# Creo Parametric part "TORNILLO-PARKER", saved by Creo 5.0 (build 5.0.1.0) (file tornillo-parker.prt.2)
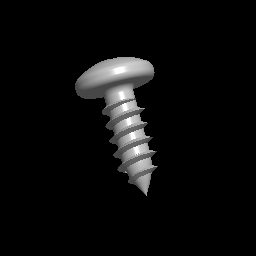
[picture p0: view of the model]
Units: millimeter Kilogram Sec (mmKs); MM, KILOGRAM, SECS
Materials in the file: FE40, ACERO

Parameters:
  TERMINACION = " Libre de rebarbas, Matar cantos vivos"
  TOLERANCIAS = "No indicadas  # 0.1  a 30'"
  MODELED_BY = "DE SANTIAGO D."
  PTC_MATERIAL_NAME = "ACERO"

Other parameters: DIAMETRO, LONGITUUD, CABEZA

Created from: PARKER-12X1_5.PRT

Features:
  1. coordinate system
  2. datum plane "RIGHT"
  3. datum plane "TOP"
  4. datum plane "FRONT"
  5. protrusion
  6. pattern
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
Family table entries: PARKER-4X0_25, 4 x 1/4, TORNILLO-PARKER, value(d_val), value(s_val), PARKER-4X0_25, value(i_val), PARKER-4X0_375, 4 x 3/8, TORNILLO-PARKER, 2/#, #PARKER-4X0_375, PARKER-4X0_5, 4 x 1/2, TORNILLO-PARKER, #PARKER-4X0_5, PARKER-4X0_625, 4 x 5/8, TORNILLO-PARKER, #PARKER-4X0_625, PARKER-4X0_75, 4 x 3/4, TORNILLO-PARKER, 2/3, #PARKER-4X0_75, PARKER-4X1, 4 x 1, TORNILLO-PARKER, #PARKER-4X1, PARKER-6X0_375, 6 x 3/8, TORNILLO-PARKER, 2/#, #PARKER-6X0_375, PARKER-6X0_5, 6 x 1/2, TORNILLO-PARKER, #PARKER-6X0_5, 2-mB, #_PARKER-6X0_5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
